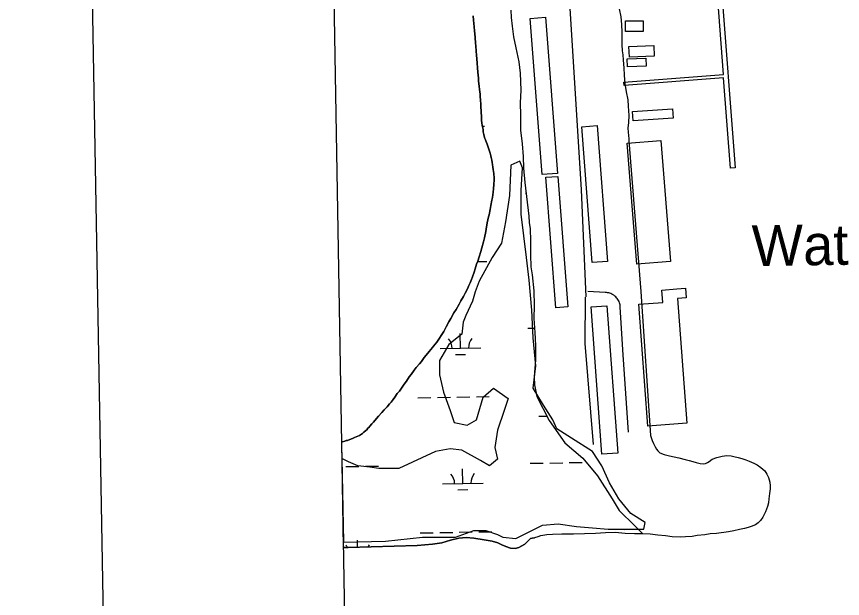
# Model space of a CAD drawing. Extents: x 3903937 to 3942190, y 260677 to 286651.
# Drawn here: x 3907281 to 3909314, y 272772 to 274205 of the extents above; entities that cross this region are included whole.
import ezdxf

# ---------------------------------------------------------------- set-up
doc = ezdxf.new("R2010")
doc.units = 0
for name, color, linetype in [('V-ANNO-SYMB', 7, 'Continuous'), ('V-BLDG-OTLN', 7, 'Continuous'), ('V-CHAN-DOCK', 7, 'Continuous'), ('V-GRID-FRAM', 7, 'Continuous'), ('V-RIVR-IDEN', 7, 'Continuous'), ('V-ROAD-CNTR', 7, 'Continuous'), ('V-SITE-VEGE', 7, 'Continuous'), ('V-TOPO-SHOR', 7, 'Continuous'), ('V-WETL-SWMP', 7, 'Continuous')]:
    doc.layers.add(name, color=color, linetype=linetype)

msp = doc.modelspace()

# ---------------------------------------------------------------- linework, layer by layer
at = {"layer": 'V-ANNO-SYMB'}
msp.add_lwpolyline([(3907684.5, 261933.3), (3940762.5, 262515.6), (3940359.2, 285428.6), (3907281.2, 284846.4), (3907684.5, 261933.3)], dxfattribs=at)
at = {"layer": 'V-BLDG-OTLN'}
for points in [[(3908613, 273818.6), (3908575.5, 273815.7), (3908545.5, 274200), (3908583, 274202.9)], [(3908780, 274194.3), (3908823.7, 274194.3), (3908823.7, 274168.1), (3908780, 274168.1)], [(3908788.7, 274130.9), (3908850, 274133.1), (3908850.9, 274106.9), (3908789.7, 274104.7)], [(3908784.4, 274100.3), (3908830.3, 274102.5), (3908831.2, 274082.8), (3908785.3, 274080.6)], [(3908797.5, 273971.2), (3908895.9, 273977.8), (3908897.5, 273954.1), (3908799.1, 273947.6)], [(3908736.1, 273601.7), (3908698, 273598.8), (3908672.8, 273933.4), (3908710.9, 273936.3)], [(3908784.4, 273892.5), (3908867.5, 273899.1), (3908891, 273601.6), (3908807.9, 273595.1)], [(3908638.1, 273490.3), (3908609, 273488), (3908584.3, 273808.9), (3908613.5, 273811.2)], [(3908812.8, 273496.7), (3908871.8, 273501.1), (3908869.6, 273531.5), (3908907, 273534.3), (3908927.9, 273535.8), (3908929.7, 273512.1), (3908908.6, 273510.5), (3908931.4, 273203.9), (3908835, 273196.7)], [(3908761.5, 273130), (3908722.4, 273127.1), (3908695.4, 273489.9), (3908734.4, 273492.8)]]:
    msp.add_lwpolyline(points, close=True, dxfattribs=at)
at = {"layer": 'V-CHAN-DOCK'}
msp.add_lwpolyline([(3908776.2, 274043.3), (3909021.9, 274062.1), (3909004.3, 274291.8), (3909015.2, 274292.6), (3909050.6, 273832.3), (3909038.4, 273831.4), (3909021.3, 274053.5), (3908776.6, 274034.7), (3908776.2, 274043.3)], dxfattribs=at)
at = {"layer": 'V-GRID-FRAM'}
msp.add_lwpolyline([(3907892.2, 284196.1), (3939773.2, 284757.2), (3940101.1, 266577.6), (3908204.3, 266016.2), (3907892.2, 284196.1)], dxfattribs=at)
at = {"layer": 'V-ROAD-CNTR'}
for points in [[(3908539.7, 275833.9), (3908558, 275646.6), (3908581.3, 275344.8), (3908596.1, 274975.2), (3908671, 273778.2), (3908682.9, 273514.6)], [(3908701.6, 273151.3), (3908680.7, 273399.5), (3908682.1, 273513.7)], [(3908787.6, 273181.5), (3908774.8, 273372.1), (3908767.4, 273489.1), (3908767.2, 273491.9), (3908766.8, 273494.8), (3908766.2, 273497.6), (3908765.3, 273500.3), (3908764.3, 273503), (3908763, 273505.5), (3908761.6, 273508), (3908760, 273510.4), (3908758.2, 273512.6), (3908756.2, 273514.7), (3908754.1, 273516.6), (3908751.9, 273518.4), (3908749.5, 273520), (3908747, 273521.4), (3908744.4, 273522.6), (3908741.7, 273523.6), (3908738.9, 273524.3), (3908736.1, 273524.9), (3908733.3, 273525.3), (3908730.5, 273525.4), (3908687.9, 273527.7)]]:
    msp.add_lwpolyline(points, dxfattribs=at)
at = {"layer": 'V-SITE-VEGE'}
msp.add_lwpolyline([(3908082.1, 273116.5), (3908085.9, 272911.2), (3908189.5, 272913.7), (3908280.3, 272923.4), (3908361.4, 272923.4), (3908406.9, 272939.6), (3908436.1, 272939.6), (3908465.3, 272929.9), (3908478.2, 272923.4), (3908510.7, 272920.2), (3908575.6, 272952.6), (3908614.5, 272955.9), (3908659.9, 272949.4), (3908698.9, 272946.1), (3908737.8, 272942.9), (3908802.7, 272942.9), (3908825.4, 272942.9), (3908828.7, 272959.1), (3908793, 272981.8), (3908763.8, 273017.5), (3908741.1, 273056.5), (3908721.6, 273098.6), (3908698.9, 273134.3), (3908647, 273166.8), (3908611.3, 273189.5), (3908601.5, 273212.2), (3908578.8, 273247.9), (3908552.9, 273290.1), (3908559.4, 273345.2), (3908552.9, 273413.4), (3908549.6, 273481.5), (3908543.1, 273556.1), (3908536.6, 273611.3), (3908523.7, 273718.4), (3908523.7, 273776.8), (3908526.9, 273831.9), (3908520.4, 273848.2), (3908497.7, 273838.4), (3908494.5, 273763.8), (3908484.7, 273698.9), (3908475, 273647), (3908452.3, 273611.3), (3908419.8, 273552.9), (3908410.1, 273526.9), (3908403.6, 273504.2), (3908387.4, 273468.5), (3908380.9, 273452.3), (3908377.7, 273423.1), (3908345.2, 273397.1), (3908322.5, 273358.2), (3908322.5, 273322.5), (3908332.2, 273280.3), (3908348.5, 273234.9), (3908358.2, 273205.7), (3908390.6, 273199.2), (3908413.4, 273212.2), (3908429.6, 273267.4), (3908455.5, 273290.1), (3908491.2, 273264.1), (3908481.5, 273234.9), (3908465.3, 273186.2), (3908458.8, 273144.1), (3908465.3, 273114.9), (3908445.8, 273098.6), (3908423.1, 273111.6), (3908377.7, 273137.6), (3908348.5, 273140.8), (3908312.8, 273134.3), (3908221.9, 273092.1), (3908208.9, 273092.1), (3908173.2, 273092.1), (3908150.5, 273095.4), (3908121.3, 273098.6), (3908098.6, 273108.4), (3908082.1, 273116.5)], dxfattribs=at)
at = {"layer": 'V-TOPO-SHOR'}
for points in [[(3908765, 274223.4), (3908768.7, 274203.8), (3908770.8, 274185), (3908771, 274166.1)], [(3908405.1, 274206.3), (3908406, 274195.8), (3908407.6, 274179.1), (3908408.2, 274169.3), (3908409.8, 274153.4), (3908411.1, 274138), (3908411.7, 274133.1), (3908413, 274118.9), (3908413.6, 274110.3), (3908414.7, 274090), (3908415.6, 274078.6), (3908416.6, 274068), (3908417.2, 274060.3), (3908418.2, 274052.6), (3908418.8, 274045.3), (3908420.1, 274033.1), (3908420.7, 274025.3), (3908422.1, 274013.9), (3908422.7, 274007), (3908423.3, 273999.3), (3908424.3, 273988.3), (3908424.5, 273981.4), (3908424.7, 273972.1), (3908425.3, 273966.8), (3908425.6, 273961.1), (3908425.5, 273957), (3908425.8, 273953.4), (3908426.1, 273949.3)], [(3908771, 274166.1), (3908771.2, 274150.7), (3908771.3, 274135.8), (3908772.3, 274120.1), (3908773.5, 274110.7), (3908774.8, 274096.9), (3908776.2, 274078.4), (3908776.8, 274060.4), (3908778.9, 274039.9), (3908782.3, 274019.5), (3908785.6, 273999.5), (3908787, 273984.2), (3908788.4, 273961.4), (3908787.7, 273944.1), (3908786.3, 273929.9), (3908786.8, 273920.1), (3908787.7, 273911.8), (3908788.1, 273903.6), (3908788.6, 273898.9), (3908817.8, 273527.6), (3908841.7, 273173.1), (3908846.1, 273161.4), (3908849.3, 273153.5), (3908853, 273145.7), (3908856.6, 273139.8), (3908859.7, 273135.5), (3908864.9, 273130.9), (3908875.2, 273127), (3908888.6, 273123.2), (3908900.4, 273120.6), (3908911.4, 273118.4), (3908926.8, 273114.2), (3908936.7, 273111.5), (3908945.7, 273109.3), (3908954, 273107), (3908963.9, 273104.3), (3908972.5, 273103.6), (3908976.8, 273104.8), (3908981.9, 273106.9), (3908986.2, 273109.7), (3908994, 273114.8), (3909005, 273119.3), (3909017.9, 273122.9), (3909030.1, 273124.2), (3909040.4, 273123.6), (3909047.1, 273121.7), (3909057.7, 273119.4), (3909066.8, 273117.1), (3909076.6, 273113.7), (3909084.9, 273110.6), (3909096, 273105.2), (3909104.3, 273101), (3909113.8, 273094.8), (3909122.9, 273086.2), (3909128.5, 273078.4)], [(3908426.1, 273949.3), (3908426.7, 273942.4), (3908427.4, 273937.1), (3908429.3, 273929.7), (3908430, 273926.5), (3908430.2, 273920.8), (3908431.3, 273914.3), (3908432, 273910.2), (3908433.9, 273904.5), (3908435.4, 273901.2), (3908436.6, 273898.3), (3908437.7, 273894.2), (3908439.6, 273890.5), (3908441.1, 273885.2), (3908443, 273880.3), (3908445.7, 273872.9), (3908447.2, 273868.4), (3908448.6, 273861.9), (3908449.3, 273857.8), (3908451.2, 273851.3), (3908451.8, 273845.1), (3908452.9, 273840.3), (3908453.6, 273834.1), (3908454.2, 273828), (3908456, 273817.9), (3908455.9, 273814.2), (3908457, 273810.5), (3908456.8, 273802.8), (3908456.5, 273791), (3908455.1, 273780.9), (3908454.4, 273772.4), (3908452.9, 273759.5), (3908451.5, 273753), (3908449.1, 273739.7), (3908447.3, 273729.6), (3908444.5, 273716.3), (3908442.8, 273711.9), (3908439.9, 273696.9), (3908437.5, 273681.2), (3908436.1, 273675.5), (3908432.9, 273660.2), (3908431, 273649.7), (3908426.6, 273635.2), (3908423.9, 273626.3), (3908419.9, 273613.4), (3908416.4, 273602.1), (3908413.8, 273594.9), (3908409.8, 273583.6), (3908407.6, 273575.6), (3908403.6, 273563.9), (3908401, 273557.1), (3908398, 273549.5), (3908394.6, 273542.2), (3908391.1, 273534.6), (3908385.6, 273523.8), (3908381.3, 273515.8), (3908375.3, 273504.6), (3908371.1, 273497), (3908363.4, 273483.4), (3908357.9, 273475), (3908350.3, 273461.4), (3908345.6, 273453), (3908339.2, 273441), (3908332.8, 273429.4), (3908328.2, 273421.8), (3908321, 273410.2), (3908315.9, 273403), (3908308, 273393.1), (3908305, 273389.9), (3908297.1, 273380.4), (3908289.5, 273371.2), (3908284.5, 273365.3), (3908277.8, 273355.7), (3908272.8, 273349.7), (3908265.2, 273340.6), (3908260.2, 273334.2), (3908252.6, 273323.9), (3908247.6, 273317.5), (3908240.8, 273307.1), (3908235.8, 273300), (3908228.6, 273290), (3908223.6, 273282.8), (3908218.5, 273276.5), (3908212.2, 273267.7), (3908208.4, 273262.1), (3908203, 273255.3), (3908199.2, 273251.4), (3908193.3, 273243.8), (3908186.2, 273236.3), (3908180.8, 273230.3), (3908172.5, 273220.8), (3908167, 273214.9), (3908160.3, 273206.5), (3908156.2, 273202.2), (3908151.1, 273196.2), (3908148.6, 273193), (3908146.1, 273191.1), (3908143.2, 273187.5), (3908140.7, 273185.5), (3908136.5, 273181.2), (3908132.8, 273178.4)], [(3908132.8, 273178.4), (3908125.8, 273173.3), (3908121.3, 273171.4), (3908113.5, 273168.3), (3908108.6, 273166.4), (3908101.6, 273163.8), (3908095.9, 273161.5), (3908092.6, 273160.8), (3908089.3, 273159.6), (3908084, 273158.1), (3908081.7, 273157.5)], [(3909128.5, 273078.4), (3909132.5, 273070.2), (3909135.4, 273058.8), (3909136.6, 273049.8), (3909136.7, 273041.9), (3909134.5, 273030.9), (3909133.4, 273017.5), (3909131.9, 273007.7), (3909130, 272999), (3909124.7, 272985.6), (3909118.1, 272972.5), (3909112.3, 272964.2), (3909106.8, 272958.7), (3909100.2, 272953.9), (3909089.6, 272949.8), (3909082.2, 272947), (3909073.6, 272944.6), (3909061, 272941.7), (3909047.3, 272938.8), (3909033.5, 272936.7), (3909004.1, 272932.5), (3908988.4, 272931.2), (3908975.4, 272929.1), (3908956.6, 272926.9), (3908944, 272925.2), (3908928.3, 272923.9), (3908914.5, 272923), (3908895.2, 272924.3), (3908878.7, 272926.1), (3908859.8, 272927.9), (3908840.9, 272930.5), (3908822.8, 272931.1), (3908808.8, 272931.2)], [(3908086.2, 272897.4), (3908097.7, 272897.5), (3908267.7, 272902.4), (3908304.9, 272905.8), (3908328.5, 272909.4), (3908349.2, 272915.8), (3908370.2, 272920.5), (3908387.8, 272922), (3908406.5, 272920.8), (3908432.4, 272916.7), (3908452.1, 272913.3), (3908466, 272909.4), (3908476.1, 272904.5), (3908485.8, 272900), (3908497.5, 272896.3), (3908508.5, 272895.2), (3908518, 272897.5), (3908532.2, 272905.9), (3908537.3, 272910.8), (3908541.3, 272915.1), (3908546.1, 272919.8), (3908550.7, 272920.7), (3908556, 272921.6)], [(3908808.8, 272931.2), (3908802.8, 272931.3), (3908779.2, 272932.6), (3908754.8, 272934.4), (3908730.8, 272934.1), (3908706.8, 272931.9), (3908679.7, 272931.3), (3908652.6, 272930.6), (3908623.5, 272930.7), (3908600.7, 272930.1), (3908586.9, 272928.8), (3908576.7, 272927.1), (3908571.2, 272926.3), (3908564.5, 272924.3), (3908556, 272921.6)]]:
    msp.add_lwpolyline(points, dxfattribs=at)
at = {"layer": 'V-WETL-SWMP'}
for p, q in [((3908406, 274195.8), (3908405.1, 274206.3)), ((3908498, 274220.6), (3908499, 274202.5)), ((3908499, 274202.5), (3908501.2, 274180.9)), ((3908407.6, 274179.1), (3908406, 274195.8)), ((3908408.2, 274169.3), (3908407.6, 274179.1)), ((3908409.8, 274153.4), (3908408.2, 274169.3)), ((3908501.2, 274180.9), (3908504.6, 274155)), ((3908411.1, 274138), (3908409.8, 274153.4)), ((3908504.6, 274155), (3908510.3, 274127.6)), ((3908411.7, 274133.1), (3908411.1, 274138)), ((3908413, 274118.9), (3908411.7, 274133.1)), ((3908510.3, 274127.6), (3908517.3, 274093.4)), ((3908413.6, 274110.3), (3908413, 274118.9)), ((3908414.7, 274090), (3908413.6, 274110.3)), ((3908415.6, 274078.6), (3908414.7, 274090)), ((3908517.3, 274093.4), (3908521.2, 274064.8)), ((3908416.6, 274068), (3908415.6, 274078.6)), ((3908417.2, 274060.3), (3908416.6, 274068)), ((3908418.2, 274052.6), (3908417.2, 274060.3)), ((3908521.2, 274064.8), (3908522.7, 274023.5)), ((3908418.8, 274045.3), (3908418.2, 274052.6)), ((3908420.1, 274033.1), (3908418.8, 274045.3)), ((3908420.7, 274025.3), (3908420.1, 274033.1)), ((3908422.1, 274013.9), (3908420.7, 274025.3)), ((3908522.7, 274023.5), (3908521.1, 273992.1)), ((3908422.7, 274007), (3908422.1, 274013.9)), ((3908423.3, 273999.3), (3908422.7, 274007)), ((3908424.3, 273988.3), (3908423.3, 273999.3)), ((3908424.5, 273981.4), (3908424.3, 273988.3)), ((3908424.7, 273972.1), (3908424.5, 273981.4)), ((3908521.1, 273992.1), (3908521.4, 273962.2)), ((3908425.3, 273966.8), (3908424.7, 273972.1)), ((3908425.6, 273961.1), (3908425.3, 273966.8)), ((3908425.5, 273957), (3908425.6, 273961.1)), ((3908521.4, 273962.2), (3908521.7, 273925.3)), ((3908425.8, 273953.4), (3908425.5, 273957)), ((3908426.1, 273949.3), (3908425.8, 273953.4)), ((3908426.7, 273942.4), (3908426.1, 273949.3)), ((3908427.4, 273937.1), (3908426.7, 273942.4)), ((3908429.3, 273929.7), (3908427.4, 273937.1)), ((3908428.1, 273934.5), (3908433.3, 273934.6)), ((3908430, 273926.5), (3908429.3, 273929.7)), ((3908430.2, 273920.8), (3908430, 273926.5)), ((3908431.3, 273914.3), (3908430.2, 273920.8)), ((3908521.7, 273925.3), (3908525.6, 273891.5)), ((3908432, 273910.2), (3908431.3, 273914.3)), ((3908433.9, 273904.5), (3908432, 273910.2)), ((3908435.4, 273901.2), (3908433.9, 273904.5)), ((3908436.6, 273898.3), (3908435.4, 273901.2)), ((3908437.7, 273894.2), (3908436.6, 273898.3)), ((3908439.6, 273890.5), (3908437.7, 273894.2)), ((3908441.1, 273885.2), (3908439.6, 273890.5)), ((3908443, 273880.3), (3908441.1, 273885.2)), ((3908445.7, 273872.9), (3908443, 273880.3)), ((3908525.6, 273891.5), (3908528.3, 273860.1)), ((3908447.2, 273868.4), (3908445.7, 273872.9)), ((3908448.6, 273861.9), (3908447.2, 273868.4)), ((3908449.3, 273857.8), (3908448.6, 273861.9)), ((3908451.2, 273851.3), (3908449.3, 273857.8)), ((3908528.3, 273860.1), (3908529.3, 273831)), ((3908451.8, 273845.1), (3908451.2, 273851.3)), ((3908452.9, 273840.3), (3908451.8, 273845.1)), ((3908453.6, 273834.1), (3908452.9, 273840.3)), ((3908454.2, 273828), (3908453.6, 273834.1)), ((3908456, 273817.9), (3908454.2, 273828)), ((3908455.9, 273814.2), (3908456, 273817.9)), ((3908529.3, 273831), (3908532.8, 273796.1)), ((3908457, 273810.5), (3908455.9, 273814.2)), ((3908456.5, 273791), (3908456.8, 273802.8)), ((3908456.8, 273802.8), (3908457, 273810.5)), ((3908532.8, 273796.1), (3908541.9, 273713.6)), ((3908454.4, 273772.4), (3908455.1, 273780.9)), ((3908455.1, 273780.9), (3908456.5, 273791)), ((3908451.5, 273753), (3908452.9, 273759.5)), ((3908452.9, 273759.5), (3908454.4, 273772.4)), ((3908534.2, 273770.2), (3908535.7, 273770.2)), ((3908447.3, 273729.6), (3908449.1, 273739.7)), ((3908449.1, 273739.7), (3908451.5, 273753)), ((3908442.7, 273711.9), (3908444.5, 273716.3)), ((3908444.5, 273716.3), (3908447.3, 273729.6)), ((3908437.5, 273681.1), (3908439.9, 273696.9)), ((3908439.9, 273696.9), (3908442.7, 273711.9)), ((3908541.9, 273713.6), (3908543.2, 273697.9)), ((3908543.2, 273697.9), (3908545.3, 273681.8)), ((3908432.9, 273660.2), (3908436.1, 273675.5)), ((3908436.1, 273675.5), (3908437.5, 273681.1)), ((3908545.3, 273681.8), (3908546.8, 273652.8)), ((3908431, 273649.7), (3908432.9, 273660.2)), ((3908423.9, 273626.3), (3908426.6, 273635.2)), ((3908426.6, 273635.2), (3908431, 273649.7)), ((3908546.8, 273652.8), (3908546, 273617.8)), ((3908416.4, 273602.1), (3908419.9, 273613.4)), ((3908419.9, 273613.4), (3908423.9, 273626.3)), ((3908546, 273617.8), (3908547.4, 273588.3)), ((3908409.8, 273583.6), (3908413.8, 273594.9)), ((3908413.8, 273594.9), (3908416.4, 273602.1)), ((3908416.2, 273601.5), (3908439.2, 273602)), ((3908403.6, 273563.9), (3908407.6, 273575.6)), ((3908407.6, 273575.6), (3908409.8, 273583.6)), ((3908547.4, 273588.3), (3908550.4, 273568.7)), ((3908398, 273549.5), (3908401, 273557.1)), ((3908401, 273557.1), (3908403.6, 273563.9)), ((3908550.4, 273568.7), (3908554.3, 273529.8)), ((3908385.6, 273523.8), (3908391.1, 273534.6)), ((3908391.1, 273534.6), (3908394.6, 273542.2)), ((3908394.6, 273542.2), (3908398, 273549.5)), ((3908375.3, 273504.6), (3908381.3, 273515.8)), ((3908381.3, 273515.8), (3908385.6, 273523.8)), ((3908554.3, 273529.8), (3908555.8, 273493.7)), ((3908363.4, 273483.4), (3908371.1, 273497)), ((3908371.1, 273497), (3908375.3, 273504.6)), ((3908555.8, 273493.7), (3908554.6, 273461.4)), ((3908350.3, 273461.4), (3908357.9, 273475)), ((3908357.9, 273475), (3908363.4, 273483.4)), ((3908339.2, 273441), (3908345.6, 273453)), ((3908345.6, 273453), (3908350.3, 273461.4)), ((3908554.6, 273461.4), (3908556.9, 273427.3)), ((3908332.8, 273429.4), (3908339.2, 273441)), ((3908540, 273437.5), (3908556.2, 273437.8)), ((3908315.9, 273403), (3908321, 273410.2)), ((3908321, 273410.2), (3908328.2, 273421.8)), ((3908328.2, 273421.8), (3908332.8, 273429.4)), ((3908373.8, 273388.2), (3908373.2, 273424.2)), ((3908556.9, 273427.3), (3908558.4, 273395)), ((3908297.1, 273380.4), (3908305, 273389.9)), ((3908305, 273389.9), (3908308, 273393.1)), ((3908308, 273393.1), (3908315.9, 273403)), ((3908558.4, 273395), (3908558.7, 273359.3)), ((3908284.5, 273365.3), (3908289.5, 273371.2)), ((3908289.5, 273371.2), (3908297.1, 273380.4)), ((3908323.8, 273387.3), (3908423.8, 273389)), ((3908362.1, 273372.5), (3908386.1, 273372.9)), ((3908265.2, 273340.6), (3908272.8, 273349.7)), ((3908272.8, 273349.7), (3908277.8, 273355.7)), ((3908277.8, 273355.7), (3908284.5, 273365.3)), ((3908558.7, 273359.3), (3908555.6, 273318)), ((3908252.6, 273323.9), (3908260.2, 273334.2)), ((3908260.2, 273334.2), (3908265.2, 273340.6)), ((3908240.8, 273307.1), (3908247.6, 273317.5)), ((3908247.6, 273317.5), (3908252.6, 273323.9)), ((3908555.6, 273318), (3908556.2, 273298)), ((3908223.6, 273282.8), (3908228.6, 273290)), ((3908228.6, 273290), (3908235.8, 273300)), ((3908235.8, 273300), (3908240.8, 273307.1)), ((3908556.2, 273298), (3908561.8, 273269.1)), ((3908208.4, 273262.1), (3908212.2, 273267.7)), ((3908212.2, 273267.7), (3908218.5, 273276.5)), ((3908218.5, 273276.5), (3908223.6, 273282.8)), ((3908317.1, 273267.1), (3908349.1, 273267.6)), ((3908365.1, 273267.9), (3908397.1, 273268.5)), ((3908413.1, 273268.8), (3908445, 273269.3)), ((3908561.8, 273269.1), (3908592.7, 273210.2)), ((3908193.3, 273243.8), (3908199.2, 273251.4)), ((3908199.2, 273251.4), (3908203, 273255.3)), ((3908203, 273255.3), (3908208.4, 273262.1)), ((3908269.1, 273266.2), (3908301.1, 273266.8)), ((3908172.5, 273220.8), (3908180.8, 273230.3)), ((3908180.8, 273230.3), (3908186.2, 273236.3)), ((3908186.2, 273236.3), (3908193.3, 273243.8)), ((3908156.2, 273202.2), (3908160.3, 273206.5)), ((3908160.3, 273206.5), (3908167, 273214.9)), ((3908167, 273214.9), (3908172.5, 273220.8)), ((3908567.2, 273220.7), (3908587, 273221.1)), ((3908592.7, 273210.2), (3908631.1, 273155.6)), ((3908140.7, 273185.5), (3908143.2, 273187.5)), ((3908143.2, 273187.5), (3908146.1, 273191.1)), ((3908146.1, 273191.1), (3908148.6, 273193)), ((3908148.6, 273193), (3908151.1, 273196.2)), ((3908151.1, 273196.2), (3908156.2, 273202.2)), ((3908101.6, 273163.8), (3908108.6, 273166.4)), ((3908108.6, 273166.4), (3908113.5, 273168.3)), ((3908113.5, 273168.3), (3908121.3, 273171.4)), ((3908121.3, 273171.4), (3908125.8, 273173.3)), ((3908125.8, 273173.3), (3908132.8, 273178.4)), ((3908132.8, 273178.4), (3908136.5, 273181.2)), ((3908136.5, 273181.2), (3908140.7, 273185.5)), ((3908081.7, 273157.5), (3908084, 273158.1)), ((3908086.2, 272897.4), (3908081.7, 273157.5)), ((3908084, 273158.1), (3908089.3, 273159.6)), ((3908089.3, 273159.6), (3908092.6, 273160.8)), ((3908092.6, 273160.8), (3908095.9, 273161.5)), ((3908095.9, 273161.5), (3908101.6, 273163.8)), ((3908631.1, 273155.6), (3908675.6, 273117.7)), ((3908545.9, 273104.9), (3908577.9, 273105.5)), ((3908593.9, 273105.7), (3908625.9, 273106.3)), ((3908641.9, 273106.6), (3908673.8, 273107.2)), ((3908675.6, 273117.7), (3908711.7, 273074.3)), ((3908092, 273096.9), (3908124, 273097.5)), ((3908140, 273097.8), (3908172, 273098.3)), ((3908379.6, 273055.5), (3908379, 273091.5)), ((3908711.7, 273074.3), (3908747.4, 273017.8)), ((3908329.7, 273054.7), (3908429.6, 273056.4)), ((3908367.9, 273039.9), (3908391.9, 273040.3)), ((3908747.4, 273017.8), (3908764.9, 272988.9)), ((3908764.9, 272988.9), (3908802.9, 272950.9)), ((3908776.8, 272942.4), (3908808.8, 272943)), ((3908802.9, 272950.9), (3908822.8, 272931.1)), ((3908274.9, 272933.6), (3908306.9, 272934.2)), ((3908322.9, 272934.5), (3908354.9, 272935)), ((3908387.8, 272922), (3908370.2, 272920.5)), ((3908370.9, 272935.3), (3908402.9, 272935.9)), ((3908406.5, 272920.8), (3908387.8, 272922)), ((3908418.9, 272936.1), (3908450.9, 272936.7)), ((3908556, 272921.6), (3908550.7, 272920.7)), ((3908564.5, 272924.3), (3908556, 272921.6)), ((3908571.2, 272926.3), (3908564.5, 272924.3)), ((3908576.7, 272927.1), (3908571.2, 272926.3)), ((3908586.9, 272928.8), (3908576.7, 272927.1)), ((3908600.7, 272930.1), (3908586.9, 272928.8)), ((3908623.5, 272930.7), (3908600.7, 272930.1)), ((3908652.6, 272930.6), (3908623.5, 272930.7)), ((3908679.7, 272931.3), (3908652.6, 272930.6)), ((3908706.8, 272931.9), (3908679.7, 272931.3)), ((3908730.8, 272934.1), (3908706.8, 272931.9)), ((3908754.8, 272934.4), (3908730.8, 272934.1)), ((3908779.2, 272932.6), (3908754.8, 272934.4)), ((3908802.8, 272931.3), (3908779.2, 272932.6)), ((3908822.8, 272931.1), (3908802.8, 272931.3)), ((3908267.7, 272902.4), (3908097.7, 272897.5)), ((3908120.9, 272898.2), (3908120.6, 272916.1)), ((3908304.9, 272905.8), (3908267.7, 272902.4)), ((3908328.5, 272909.4), (3908304.9, 272905.8)), ((3908349.2, 272915.8), (3908328.5, 272909.4)), ((3908370.2, 272920.5), (3908349.2, 272915.8)), ((3908432.4, 272916.7), (3908406.5, 272920.8)), ((3908452.1, 272913.3), (3908432.4, 272916.7)), ((3908466, 272909.4), (3908452.1, 272913.3)), ((3908476.1, 272904.5), (3908466, 272909.4)), ((3908485.8, 272900), (3908476.1, 272904.5)), ((3908532.2, 272905.9), (3908518, 272897.5)), ((3908537.3, 272910.8), (3908532.2, 272905.9)), ((3908541.3, 272915.1), (3908537.3, 272910.8)), ((3908546.1, 272919.8), (3908541.3, 272915.1)), ((3908550.7, 272920.7), (3908546.1, 272919.8)), ((3908097.7, 272897.5), (3908086.2, 272897.4)), ((3908497.5, 272896.3), (3908485.8, 272900)), ((3908508.5, 272895.2), (3908497.5, 272896.3)), ((3908518, 272897.5), (3908508.5, 272895.2))]:
    msp.add_line(p, q, dxfattribs=at)
for centre, start, end in [((3908318.5, 273387.7), 0.2366, 41.7802), ((3908429, 273389.6), 140.2366, 181.7802), ((3908324.4, 273055), 0.2366, 41.7802), ((3908434.9, 273057), 140.2366, 181.7802), ((3908066, 272879.7), 30.3833, 41.7802), ((3908176.5, 272881.6), 140.2366, 150.625)]:
    msp.add_arc(centre, 35.2, start, end, dxfattribs=at)

# ---------------------------------------------------------------- texts
at = {"layer": 'V-RIVR-IDEN'}
msp.add_text('Water', height=100, rotation=0.8184, dxfattribs=at).set_placement((3909091.9, 273590.3))

doc.saveas('drawing.dxf')
